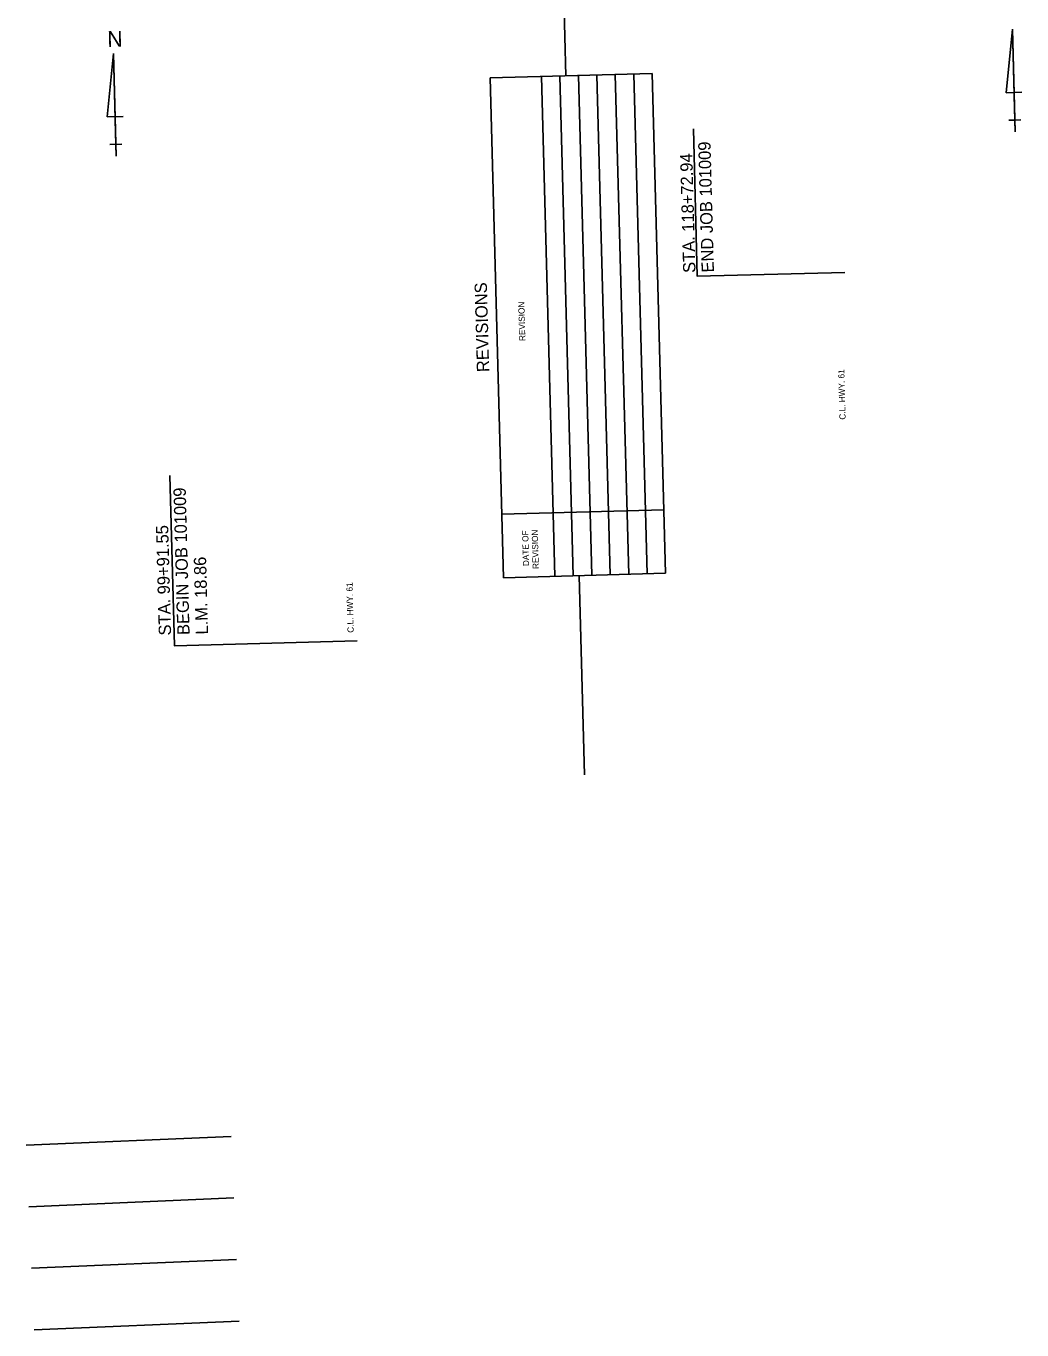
# Model space of a CAD drawing. Extents: x 1930579 to 1931596, y 596452 to 598574.
# Drawn here: x 1930579 to 1931549, y 596452 to 597722 of the extents above; entities that cross this region are included whole.
import ezdxf

# ---------------------------------------------------------------- set-up
doc = ezdxf.new("R2010")
doc.units = 0
for name, color, linetype in [('Default', 7, 'Continuous'), ('S_BASELINE', 7, 'Continuous'), ('S_BRIDGE', 7, 'Continuous'), ('S_PRIMARY_CTL_ANNOT', 7, 'Continuous'), ('S_SIDE_DRAIN', 7, 'Continuous')]:
    doc.layers.add(name, color=color, linetype=linetype)

msp = doc.modelspace()

# ---------------------------------------------------------------- linework, layer by layer
at = {"layer": 'S_BASELINE'}
for p, q in [((1931105.2, 597673), (1931089, 598275.8)), ((1931540.1, 597718.4), (1931534, 597656.6)), ((1931542.8, 597618.4), (1931540.1, 597718.4)), ((1931540.1, 597718.4), (1931542.1, 597641.5)), ((1930664.6, 597694.9), (1930658.5, 597633.1)), ((1930667.3, 597594.9), (1930664.6, 597694.9)), ((1930664.6, 597694.9), (1930666.6, 597618)), ((1931534, 597656.6), (1931549.4, 597657)), ((1931542.8, 597618.4), (1931542.1, 597641.5)), ((1930658.5, 597633.1), (1930673.9, 597633.5)), ((1931536.7, 597629.8), (1931548.2, 597630.1)), ((1931542.4, 597629.9), (1931536.7, 597629.8)), ((1931542.8, 597618.4), (1931542.4, 597629.9)), ((1930667.3, 597594.9), (1930666.6, 597618)), ((1930661.2, 597606.3), (1930672.7, 597606.6)), ((1930667, 597606.4), (1930661.2, 597606.3)), ((1930667.3, 597594.9), (1930667, 597606.4)), ((1931123.5, 596992.3), (1931118.2, 597186.3))]:
    msp.add_line(p, q, dxfattribs=at)
at = {"layer": 'S_BRIDGE'}
for points in [[(1931376.9, 597481.7), (1931233.2, 597477.9), (1931229.4, 597621.5)], [(1930901.9, 597122.9), (1930724, 597118.1), (1930719.5, 597283.8)]]:
    msp.add_lwpolyline(points, dxfattribs=at)
at = {"layer": 'S_PRIMARY_CTL_ANNOT'}
for p, q in [((1930779.3, 596640.3), (1930579.5, 596631.6)), ((1930781.9, 596580.4), (1930582.1, 596571.7)), ((1930784.5, 596520.4), (1930584.7, 596511.8)), ((1930787.1, 596460.5), (1930587.3, 596451.8))]:
    msp.add_line(p, q, dxfattribs=at)
at = {"layer": 'S_SIDE_DRAIN'}
for p, q in [((1931031.4, 597671), (1931189.3, 597675.2)), ((1931112.4, 597186.2), (1931099.4, 597672.8)), ((1931130.4, 597186.7), (1931117.4, 597673.3)), ((1931148.4, 597187.1), (1931135.4, 597673.8)), ((1931166.4, 597187.6), (1931153.4, 597674.2)), ((1931184.4, 597188.1), (1931171.4, 597674.7)), ((1931202.4, 597188.6), (1931189.3, 597675.2)), ((1931044.5, 597184.3), (1931031.4, 597671)), ((1931094.5, 597185.7), (1931081.4, 597672.3)), ((1931042.8, 597246.1), (1931200.8, 597250.4)), ((1931044.5, 597184.3), (1931202.4, 597188.6))]:
    msp.add_line(p, q, dxfattribs=at)

# ---------------------------------------------------------------- texts
at = {"layer": 'Default'}
for s, p in [('STA. 118+72.94', (1931231.5, 597481.3)), ('END JOB 101009', (1931249.5, 597481.7)), ('BEGIN JOB 101009', (1930738.8, 597128.7)), ('STA. 99+91.55', (1930720.8, 597128.2)), ('L.M. 18.86', (1930756.8, 597129.1))]:
    msp.add_text(s, height=12, rotation=91.5377, dxfattribs=at).set_placement(p)
at = {"layer": 'S_BASELINE'}
msp.add_text('N', height=15.4, rotation=1.5377, dxfattribs=at).set_placement((1930658.8, 597701.1))
at = {"layer": 'S_BRIDGE'}
for rotation, p in [(91.5377, (1931377.7, 597338.3)), (91.3975, (1930898.6, 597130.8))]:
    msp.add_text('C.L. HWY. 61', height=6, rotation=rotation, dxfattribs=at).set_placement(p)
at = {"layer": 'S_SIDE_DRAIN'}
for s, height, p in [('REVISIONS', 12, (1931030.6, 597384.7)), ('REVISION', 6, (1931065.8, 597414.9)), ('DATE OF', 6, (1931069.5, 597195.7)), ('REVISION', 6, (1931078.9, 597192.9))]:
    msp.add_text(s, height=height, rotation=91.5377, dxfattribs=at).set_placement(p)

doc.saveas('drawing.dxf')
